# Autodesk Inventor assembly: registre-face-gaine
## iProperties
Author: chr
Created: 2001-06
Part Number: registre-face-gaine
Document SubType Name: Assemblage
Designer: chr
Control State: 0
Master: False
Checked Out: False
PropertySet Name: Design Tracking Control
Shininess: 21.0
PropertySet Name: _Private Model Information
Length Units: 11269
Angle Units: 11286
Time Units: 11279
Mass Units: 11290
Length Display Precision: 3
Angle Display Precision: 2
Compacted: False
Density: 0.0
Volumn: 0.0
Area: 0.0
PropertySet Name: Model Information
